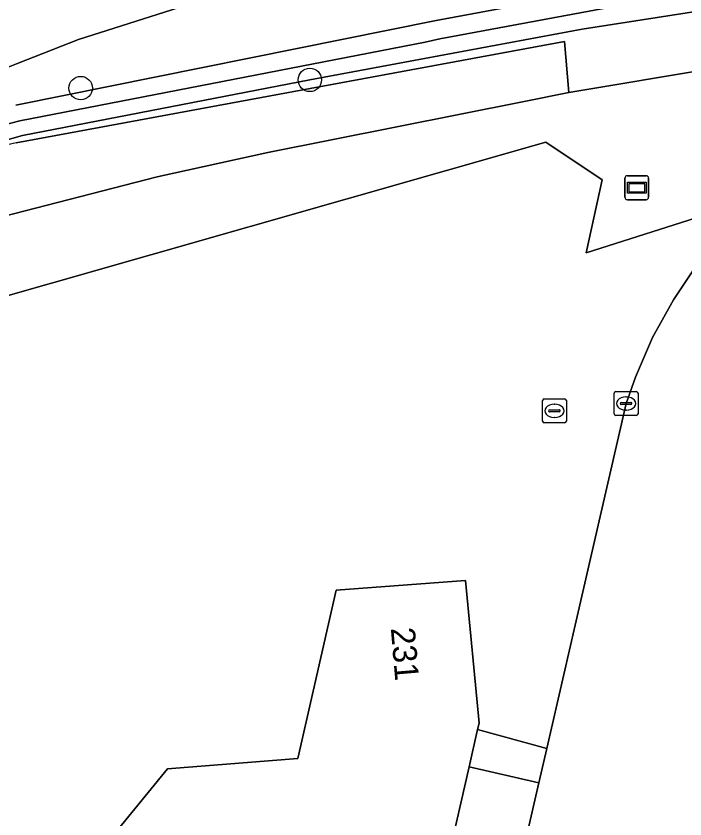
# Model space of a CAD drawing. Extents: x 161385 to 162589, y 388479 to 389756.
# Drawn here: x 162377.32 to 162405.25, y 389066.84 to 389100.37 of the extents above; entities that cross this region are included whole.
import ezdxf

# ---------------------------------------------------------------- set-up
doc = ezdxf.new("R2010")
doc.units = 0
for name, color, linetype in [('IMGEO_Berm_groen', 7, 'Continuous'), ('IMGEO_Boom', 7, 'Continuous'), ('IMGEO_Erf', 7, 'Continuous'), ('IMGEO_Grasland_overig', 7, 'Continuous'), ('IMGEO_Groenvoorziening', 7, 'Continuous'), ('IMGEO_Informatiebord', 7, 'Continuous'), ('IMGEO_Kolk', 7, 'Continuous'), ('IMGEO_Oever', 7, 'Continuous'), ('IMGEO_Pand', 7, 'Continuous'), ('IMGEO_Pand_nummerreeks', 7, 'Continuous'), ('IMGEO_Rijbaan_lokaal_gesloten', 7, 'Continuous'), ('IMGEO_Rioolput', 7, 'Continuous'), ('IMGEO_Waterloop', 7, 'Continuous')]:
    doc.layers.add(name, color=color, linetype=linetype)

msp = doc.modelspace()

# ---------------------------------------------------------------- linework, layer by layer
at = {"layer": 'IMGEO_Berm_groen'}
msp.add_lwpolyline([(162393.397, 389043.229), (162398.094, 389063.755), (162399.15, 389068.347), (162396.234, 389069.017), (162382.137, 389007.539), (162385.073, 389006.813), (162388.76, 389022.887)], close=True, dxfattribs=at)
at = {"layer": 'IMGEO_Boom'}
for centre in [(162389.587, 389097.707), (162380.021, 389097.364)]:
    msp.add_circle(centre, 0.489, dxfattribs=at)
at = {"layer": 'IMGEO_Erf'}
msp.add_lwpolyline([(162377.126, 389060.957), (162383.65, 389068.933), (162389.08, 389069.363), (162390.69, 389076.394), (162396.09, 389076.798), (162396.653, 389070.841), (162396.592, 389070.577), (162399.481, 389069.789), (162400.663, 389074.932), (162402.792, 389084.192), (162403.178, 389085.29), (162403.9, 389086.945), (162404.767, 389088.528), (162405.772, 389090.027), (162406.907, 389091.431), (162408.163, 389092.728), (162401.128, 389090.478), (162401.799, 389093.537), (162399.442, 389095.107), (162374.638, 389088.034)], dxfattribs=at)
at = {"layer": 'IMGEO_Grasland_overig'}
msp.add_lwpolyline([(162278.061, 389034.486), (162280.023, 389034.828), (162288.647, 389035.706), (162295.435, 389039.077), (162297.306, 389040.145), (162306.39, 389045.62), (162331.997, 389060.418), (162340.523, 389066.157), (162342.156, 389066.972), (162343.709, 389067.93), (162345.171, 389069.022), (162346.529, 389070.241), (162347.773, 389071.576), (162348.632, 389072.657), (162357.656, 389083.031), (162363.851, 389089.234), (162366.896, 389092.076), (162370.937, 389095.277), (162372.4, 389096.154), (162374.82, 389097.375), (162377.339, 389098.374), (162379.935, 389099.397), (162385.624, 389101.218)], dxfattribs=at)
at = {"layer": 'IMGEO_Groenvoorziening'}
for points in [[(162377.318, 389096.648), (162394.86, 389100.187), (162432.566, 389107.183)], [(162438.603, 389104.956), (162406.149, 389100.295), (162406.403, 389098.189), (162400.404, 389097.175), (162398.535, 389096.802), (162387.833, 389094.669), (162383.219, 389093.661), (162376.278, 389091.878)], [(162385.624, 389101.218), (162379.935, 389099.397), (162377.339, 389098.374), (162374.82, 389097.375), (162372.4, 389096.154), (162370.937, 389095.277), (162366.896, 389092.076), (162363.851, 389089.234), (162357.656, 389083.031), (162348.632, 389072.657), (162347.773, 389071.576), (162346.529, 389070.241), (162345.171, 389069.022), (162343.709, 389067.93), (162342.156, 389066.972), (162340.523, 389066.157), (162331.997, 389060.418), (162306.39, 389045.62), (162297.306, 389040.145), (162295.435, 389039.077), (162288.647, 389035.706), (162280.023, 389034.828), (162278.061, 389034.486)], [(162374.638, 389088.034), (162399.442, 389095.107), (162401.799, 389093.537), (162401.128, 389090.478), (162408.163, 389092.728), (162409.014, 389093.488), (162410.447, 389094.589), (162411.972, 389095.559), (162413.578, 389096.388), (162415.251, 389097.071), (162416.979, 389097.601), (162418.747, 389097.975), (162437.54, 389099.827), (162439.314, 389099.957), (162442.907, 389100.015), (162448.362, 389099.697)], [(162400.404, 389097.175), (162400.222, 389099.308), (162377.322, 389095.078)], [(162372.075, 389092.627), (162364.808, 389084.679), (162348.12, 389067.475), (162363.443, 389080.865), (162372.943, 389089.784), (162374.882, 389091.102), (162376.278, 389091.878), (162383.219, 389093.661), (162387.833, 389094.669), (162398.535, 389096.802), (162400.404, 389097.175)]]:
    msp.add_lwpolyline(points, dxfattribs=at)
msp.add_lwpolyline([(162399.481, 389069.789), (162396.592, 389070.577), (162396.234, 389069.017), (162399.15, 389068.347)], close=True, dxfattribs=at)
msp.add_arc((162380.41, 389081.625), 13.803, 102.9291, 127.1478, dxfattribs=at)
at = {"layer": 'IMGEO_Informatiebord'}
for p, q in [((162402.843, 389093.704), (162403.633, 389093.704)), ((162403.633, 389093.704), (162402.843, 389093.704)), ((162402.743, 389092.804), (162402.743, 389093.604)), ((162402.743, 389093.604), (162402.743, 389092.804)), ((162403.733, 389093.604), (162403.733, 389092.804)), ((162403.733, 389092.804), (162403.733, 389093.604)), ((162403.633, 389092.704), (162402.843, 389092.704)), ((162402.843, 389092.704), (162403.633, 389092.704))]:
    msp.add_line(p, q, dxfattribs=at)
for points in [[(162402.844, 389093.436), (162403.632, 389093.436), (162403.632, 389092.972), (162402.844, 389092.972), (162402.844, 389093.436)], [(162402.909, 389093.371), (162402.909, 389093.037), (162403.567, 389093.037), (162403.567, 389093.371), (162402.909, 389093.371)]]:
    msp.add_lwpolyline(points, dxfattribs=at)
for centre, start, end in [((162402.843, 389093.604), 90, 180), ((162402.843, 389093.604), 90, 180), ((162403.633, 389093.604), 0, 90), ((162403.633, 389093.604), 360, 90), ((162402.843, 389092.804), 180, 270), ((162402.843, 389092.804), 180, 270), ((162403.633, 389092.804), 270, 0), ((162403.633, 389092.804), 270, 0)]:
    msp.add_arc(centre, 0.1, start, end, dxfattribs=at)
at = {"layer": 'IMGEO_Kolk'}
for p, q in [((162402.291, 389083.766), (162402.291, 389084.618)), ((162402.366, 389084.692), (162403.218, 389084.692)), ((162403.292, 389084.618), (162403.292, 389083.766)), ((162402.779, 389084.472), (162402.804, 389084.472)), ((162402.55, 389084.186), (162402.55, 389084.198)), ((162402.988, 389084.149), (162402.59, 389084.149)), ((162402.593, 389084.235), (162402.991, 389084.235)), ((162402.802, 389083.912), (162402.777, 389083.912)), ((162403.034, 389084.198), (162403.034, 389084.186)), ((162403.218, 389083.692), (162402.366, 389083.692))]:
    msp.add_line(p, q, dxfattribs=at)
for points in [[(162402.291, 389083.766), (162402.291, 389084.618)], [(162402.366, 389084.692), (162403.218, 389084.692)], [(162403.292, 389084.618), (162403.292, 389083.766)], [(162403.218, 389083.692), (162402.366, 389083.692)]]:
    msp.add_lwpolyline(points, dxfattribs=at)
for centre, radius, start, end in [((162402.368, 389084.616), 0.0765, 91.552, 178.448), ((162402.368, 389084.616), 0.0765, 91.552, 178.448), ((162403.216, 389084.616), 0.0765, 1.552, 88.448), ((162403.216, 389084.616), 0.0765, 1.552, 88.448), ((162402.59, 389084.195), 0.0403, 85.8775, 175.7526), ((162402.587, 389084.185), 0.0366, 178.938, 274.7102), ((162402.991, 389084.192), 0.043, 264.8664, 352.4533), ((162402.995, 389084.197), 0.0386, 1.7309, 96.639), ((162402.368, 389083.768), 0.0765, 181.552, 268.448), ((162402.368, 389083.768), 0.0765, 181.552, 268.448), ((162403.216, 389083.768), 0.0765, 271.552, 358.448), ((162403.216, 389083.768), 0.0765, 271.552, 358.448)]:
    msp.add_arc(centre, radius, start, end, dxfattribs=at)
for centre, major_axis, ratio, start_param, end_param in [((162402.778, 389084.192), (-0.387, 0.002), 0.722429, 4.712389, 7.853982), ((162402.803, 389084.192), (-0.39, 0.002), 0.717154, 1.570796, 4.712389)]:
    msp.add_ellipse(centre, major_axis=major_axis, ratio=ratio, start_param=start_param, end_param=end_param, dxfattribs=at)
at = {"layer": 'IMGEO_Oever'}
for points in [[(162438.603, 389104.956), (162462.452, 389098.908), (162487.431, 389089.647), (162488.169, 389091.372), (162488.778, 389092.794), (162463.695, 389102.686), (162442.099, 389108.529), (162441.985, 389108.557), (162436.446, 389107.928), (162432.566, 389107.183), (162394.86, 389100.187), (162377.318, 389096.648)], [(162347.228, 389067.619), (162347.308, 389067.704), (162348.231, 389068.546), (162371.262, 389093.088), (162372.064, 389093.778), (162374.293, 389095.17), (162377.479, 389096.001), (162394.401, 389099.278), (162395.008, 389099.423), (162432.71, 389106.418), (162436.563, 389107.158), (162440.715, 389107.629), (162442.207, 389107.406), (162463.45, 389101.946), (162486.958, 389092.675)], [(162486.565, 389090.853), (162486.503, 389090.864), (162486.356, 389090.894), (162486.213, 389090.928), (162462.684, 389099.652), (162438.645, 389105.748), (162424.166, 389103.514), (162405.34, 389100.503), (162400.959, 389099.822)], [(162377.322, 389095.078), (162400.222, 389099.308), (162400.404, 389097.175), (162406.403, 389098.189), (162406.149, 389100.295), (162438.603, 389104.956)], [(162400.959, 389099.822), (162389.587, 389097.707), (162377.586, 389095.388), (162374.412, 389094.498), (162371.925, 389093.029), (162348.025, 389067.712), (162347.462, 389067.423), (162347.36, 389067.365)]]:
    msp.add_lwpolyline(points, dxfattribs=at)
msp.add_arc((162380.41, 389081.625), 13.803, 102.9291, 127.1478, dxfattribs=at)
at = {"layer": 'IMGEO_Pand'}
msp.add_lwpolyline([(162328.936, 389025.268), (162325.326, 389009.487), (162325.259, 389009.192), (162365.365, 389000), (162372.548, 388998.354), (162379.671, 388996.721), (162380.416, 389000), (162380.909, 389002.169), (162380.966, 389002.419), (162380.537, 389002.517), (162381.667, 389007.351), (162382.07, 389007.248), (162382.137, 389007.539), (162396.234, 389069.017), (162396.592, 389070.577), (162396.653, 389070.841), (162396.09, 389076.798), (162390.69, 389076.394), (162389.08, 389069.363), (162383.65, 389068.933), (162377.126, 389060.957), (162371.545, 389065.621), (162365.408, 389058.133), (162359.823, 389062.773)], close=True, dxfattribs=at)
at = {"layer": 'IMGEO_Rijbaan_lokaal_gesloten'}
msp.add_lwpolyline([(162448.362, 389099.697), (162442.907, 389100.015), (162439.314, 389099.957), (162437.54, 389099.827), (162418.747, 389097.975), (162416.979, 389097.601), (162415.251, 389097.071), (162413.578, 389096.388), (162411.972, 389095.559), (162410.447, 389094.589), (162409.014, 389093.488), (162408.163, 389092.728), (162406.907, 389091.431), (162405.772, 389090.027), (162404.767, 389088.528), (162403.9, 389086.945), (162403.178, 389085.29), (162402.792, 389084.192), (162400.663, 389074.932), (162399.481, 389069.789), (162399.15, 389068.347), (162398.094, 389063.755)], dxfattribs=at)
at = {"layer": 'IMGEO_Rioolput'}
for p, q in [((162399.299, 389083.459), (162399.299, 389084.311)), ((162399.374, 389084.385), (162400.226, 389084.385)), ((162400.3, 389084.311), (162400.3, 389083.459)), ((162399.601, 389083.928), (162399.999, 389083.928)), ((162399.787, 389084.165), (162399.812, 389084.165)), ((162399.558, 389083.879), (162399.558, 389083.891)), ((162399.996, 389083.842), (162399.598, 389083.842)), ((162399.81, 389083.605), (162399.785, 389083.605)), ((162400.042, 389083.891), (162400.042, 389083.879)), ((162400.226, 389083.385), (162399.374, 389083.385))]:
    msp.add_line(p, q, dxfattribs=at)
for points in [[(162399.299, 389083.459), (162399.299, 389084.311)], [(162399.374, 389084.385), (162400.226, 389084.385)], [(162400.3, 389084.311), (162400.3, 389083.459)], [(162400.226, 389083.385), (162399.374, 389083.385)]]:
    msp.add_lwpolyline(points, dxfattribs=at)
for centre, radius, start, end in [((162399.376, 389084.309), 0.0765, 91.552, 178.448), ((162399.376, 389084.309), 0.0765, 91.552, 178.448), ((162400.224, 389084.309), 0.0765, 1.552, 88.448), ((162400.224, 389084.309), 0.0765, 1.552, 88.448), ((162399.598, 389083.888), 0.0403, 85.8775, 175.7526), ((162400.003, 389083.89), 0.0386, 1.7309, 96.639), ((162399.595, 389083.878), 0.0366, 178.938, 274.7102), ((162399.999, 389083.885), 0.043, 264.8664, 352.4533), ((162399.376, 389083.461), 0.0765, 181.552, 268.448), ((162399.376, 389083.461), 0.0765, 181.552, 268.448), ((162400.224, 389083.461), 0.0765, 271.552, 358.448), ((162400.224, 389083.461), 0.0765, 271.552, 358.448)]:
    msp.add_arc(centre, radius, start, end, dxfattribs=at)
for centre, major_axis, ratio, start_param, end_param in [((162399.786, 389083.885), (-0.387, 0.002), 0.722429, 4.712389, 7.853982), ((162399.811, 389083.885), (-0.39, 0.002), 0.717154, 1.570796, 4.712389)]:
    msp.add_ellipse(centre, major_axis=major_axis, ratio=ratio, start_param=start_param, end_param=end_param, dxfattribs=at)
at = {"layer": 'IMGEO_Waterloop'}
for points in [[(162486.958, 389092.675), (162463.45, 389101.946), (162442.207, 389107.406), (162440.715, 389107.629), (162436.563, 389107.158), (162432.71, 389106.418), (162395.008, 389099.423), (162394.401, 389099.278)], [(162347.36, 389067.365), (162347.462, 389067.423), (162348.025, 389067.712), (162371.925, 389093.029), (162374.412, 389094.498), (162377.586, 389095.388), (162389.587, 389097.707), (162400.959, 389099.822), (162405.34, 389100.503), (162424.166, 389103.514), (162438.645, 389105.748), (162462.684, 389099.652), (162486.213, 389090.928), (162486.356, 389090.894), (162486.503, 389090.864), (162486.565, 389090.853)], [(162394.401, 389099.278), (162377.479, 389096.001), (162374.293, 389095.17), (162372.064, 389093.778), (162371.262, 389093.088), (162348.231, 389068.546), (162347.308, 389067.704), (162347.228, 389067.619)]]:
    msp.add_lwpolyline(points, dxfattribs=at)

# ---------------------------------------------------------------- texts
at = {"layer": 'IMGEO_Pand_nummerreeks'}
msp.add_text('231', height=1, rotation=274.8592, dxfattribs=at).set_placement((162392.967, 389074.805))

doc.saveas('drawing.dxf')
